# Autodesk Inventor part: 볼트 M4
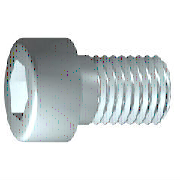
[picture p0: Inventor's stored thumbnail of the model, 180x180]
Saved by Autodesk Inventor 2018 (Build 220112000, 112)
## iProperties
IsCustomPart: 1
Created: 2012-02
Part Number: 볼트 M4
Material: 스테인리스강
Description: 6각 소켓 머리 캡 나사
Document SubType Name: Modeling
Standard: ISO 4762
Designer: mduedu
Standard Revision: Fourth edition 2004-03-01
Standards Organization: ISO
Language: ko-KR
Size Designation: M4 x 10
Categories: <MemberInstance><Categories><Category DisplayName="조임쇠" InternalName="e4da775c-781d-43d5-af7c-5136215cf5a6" Mnemonic="FSTN"><Category DisplayName="볼트" InternalN
Density: 8.08 g/cm^3
Appearance: 반광택
Mass: 2.0939 g
Surface Area: 3.06255 cm^2
Volume: 0.259146 cm^3
Author: mduedu
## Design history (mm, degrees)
sketch "스케치1"
  geometry: L1 (-1, 0)-(10, 0); L2 (10, 0)-(10, 2); L3 (10, 2)-(1.75, 2); L4 (1.75, 2)-(1.32, 2); L5 (1.32, 2)-(0, 2); L6 (0, 2)-(0, 3.5); L7 (0, 3.5)-(-4, 3.5); L8 (-4, 3.5)-(-4, 1.732); L9 (-4, 1.732)-(-2, 1.732); L10 (-2, 1.732)-(-1, 0); L11 (-6.8, 0)-(12.8, 0) reference; L12 (0, -0.7)-(0, 4.2) reference; L13 (1.75, 2)-(0, 2)
  constraints: 22 end point, 6 parallel, 2 collinear, 2 perpendicular, 1 horizontal, 1 point on line
  dimensions: "d1" = 8.25 distance from line of L3.end L2 (= GEL); "d2" = 0.42952 distance of L4.end L3.end (computed from GAL); "d3" = 4 distance between parallel lines of L8 L6 (= KOH); "d4" = 2 distance of L8.end L9.end (= INTI); "d5" = 60 deg angle of L10 L1; "d6" = 4 diameter of L3 L1 (= GD); "d7" = 4 diameter of L5 L1 (= BDM); "d8" = 3.4641 diameter of L9 L1 (= 1.1547 x SW); "d9" = 7 diameter of L7 L1 (= KOD); "d26" = 10 distance between parallel lines of L12 L2 (= NLG)
revolve "본체" sketch "스케치1" stored, may be unused: angle "d10" = 90 deg
sketch "스케치2"
  geometry: L1 (0, -4.9)-(0, 4.9) reference; L2 (-4.9, 0)-(4.9, 0) reference; L3 (1.732, 0)-(0.866, -1.5); L4 (0.866, -1.5)-(-0.866, -1.5); L5 (-0.866, -1.5)-(-1.732, 0); L6 (-1.732, 0)-(-0.866, 1.5); L7 (-0.866, 1.5)-(0.866, 1.5); L8 (0.866, 1.5)-(1.732, 0); 2 further points
  constraints: 12 end point, 1 coincident, 1 horizontal alignment, 1 point on line, 12 other
extrude "슬롯" join sketch "스케치2" stored distance "d11" = 10; taper "d12" = 0 deg
workplane "Work Plane1"
body "Solid1"
fillet "모깎기1" dims "d17" = 0.4 (= RR)
feature "스레드" dims "d13" = 8.25 (= GEL), "d14" = 0
chamfer "모따기1" distance "d15" = 0.42941 (= -0.5 x SPD + 0.5 x GD); stored, may be unused: second distance "d16" = 0.42941 (= GUL), angle "d27" = 45 deg
other parameters: "GD" = 4 [user parameter; used in 2 equation terms], "NLG" = 10 [user parameter; used in 1 equation term], "GEL" = 8.25 [user parameter; used in 2 equation terms], "KOD" = 7 [user parameter; used in 1 equation term], "KOH" = 4 [user parameter; used in 1 equation term], "INTI" = 2 [user parameter; used in 1 equation term], "GAL" = 0.42941 (= 0.61345 x PTC) [user parameter; used in 1 equation term], "GUL" = 0.42941 (= 0.61345 x PTC) [user parameter; used in 1 equation term], "BDM" = 4 (= NND) [user parameter; used in 1 equation term], "SW" = 3 [user parameter; used in 2 equation terms], "RR" = 0.4 [user parameter; used in 1 equation term], "SPD" = 3.14117 (= NND - 1.2269 x PTC) [user parameter; used in 1 equation term], "d19" = 0, "d28" = 0, "d29" = 0, "R" = 0.1 [user parameter], "TOA" = 30 deg [user parameter], "GD1" = 3.14117 (= THREADDIA - 1.2269 x PTC) [user parameter], "THREADDIA" = 4 [user parameter; used in 1 equation term], "FAWI" = 45 deg [user parameter], "TPU" = 14.28571 (computed from PTC) [user parameter], "PTC" = 0.7 [user parameter; used in 5 equation terms], "NND" = 4 [user parameter; used in 2 equation terms], "E0" = 3.465 (= 1.155 x SW) [user parameter]
